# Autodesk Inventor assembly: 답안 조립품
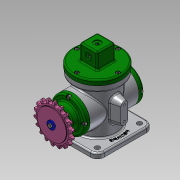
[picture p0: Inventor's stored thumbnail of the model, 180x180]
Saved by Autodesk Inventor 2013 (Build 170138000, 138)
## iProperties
Created: 2021-03
Part Number: 답안 조립품
Document SubType Name: Assembly
Designer: hana-cad24
Author: hana-cad24
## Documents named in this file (19)
- C:\Users\hana-cad24\Desktop\710306V1016\답안 조립품.iam
- C:\Users\hana-cad24\Desktop\710306V1016\본체.ipt
- C:\Users\hana-cad24\Desktop\710306V1016\편심축.ipt
- C:\Users\hana-cad24\Desktop\710306V1016\베어링 17 x 40 x 12.ipt
- C:\Users\hana-cad24\Desktop\710306V1016\앞커버.ipt
- C:\Users\hana-cad24\Desktop\710306V1016\뒤커버.ipt
- C:\Users\hana-cad24\Desktop\710306V1016\오일 실 17 30 8.ipt
- C:\Users\hana-cad24\Desktop\710306V1016\키 4 x 4 x 12.ipt
- C:\Users\hana-cad24\Desktop\710306V1016\스프로킷.ipt
- C:\Users\hana-cad24\Desktop\710306V1016\멈춤나사 M3.ipt
- C:\Users\hana-cad24\Desktop\710306V1016\와셔 4x16.ipt
- C:\Users\hana-cad24\Desktop\710306V1016\볼트 M4 x 8.ipt
- C:\Users\hana-cad24\Desktop\710306V1016\볼트 M4 x 10.ipt
- C:\Users\hana-cad24\Desktop\710306V1016\링크.ipt
- C:\Users\hana-cad24\Desktop\710306V1016\클레비스 핀 6 x 22.ipt
- 클레비스 핀 6 x 22.ipt
- C:\Users\hana-cad24\Desktop\710306V1016\슬라이더.ipt
- C:\Users\hana-cad24\Desktop\710306V1016\E-링.ipt
- C:\Users\hana-cad24\Desktop\710306V1016\덮개.ipt
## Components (1 placed, 1 different names)
1. E-링:1
